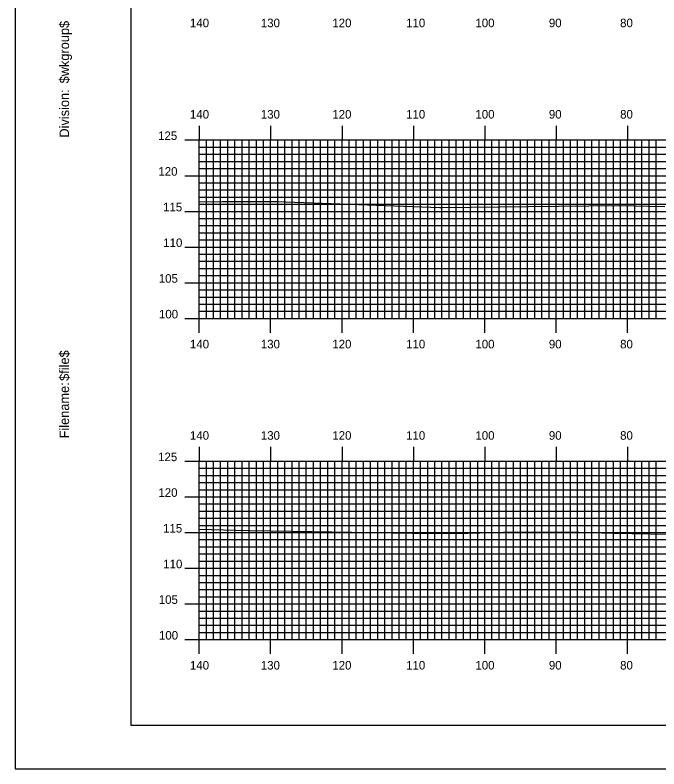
# Model space of a CAD drawing. Extents: x 1779893 to 1780236, y 442591 to 442811.
# Drawn here: x 1779892.6 to 1779982.7, y 442590.5 to 442696.2 of the extents above; entities that cross this region are included whole.
import ezdxf

# ---------------------------------------------------------------- set-up
doc = ezdxf.new("R2010")
doc.units = 0
for name, color, linetype in [('BORDER', 7, 'Continuous'), ('H_V ANNOTATION', 7, 'Continuous'), ('MAJOR', 7, 'Continuous'), ('MINOR', 7, 'Continuous'), ('PLOT BOUNDARY', 7, 'Continuous'), ('S_Roadway_Centerline', 7, 'Continuous')]:
    doc.layers.add(name, color=color, linetype=linetype)

msp = doc.modelspace()

# ---------------------------------------------------------------- linework, layer by layer
at = {"layer": 'BORDER'}
msp.add_lwpolyline([(1779908.76, 442596.67), (1780228.76, 442596.67), (1780228.76, 442806.67), (1779908.76, 442806.67)], close=True, dxfattribs=at)
at = {"layer": 'MAJOR'}
for p, q in [((1779918.36, 442680.67), (1779918.36, 442678.67)), ((1779928.36, 442680.67), (1779928.36, 442678.67)), ((1779938.36, 442680.67), (1779938.36, 442678.67)), ((1779948.36, 442680.67), (1779948.36, 442678.67)), ((1779958.36, 442680.67), (1779958.36, 442678.67)), ((1779968.36, 442680.67), (1779968.36, 442678.67)), ((1779978.36, 442680.67), (1779978.36, 442678.67)), ((1779916.35, 442678.67), (1779918.36, 442678.67)), ((1779918.36, 442678.67), (1780198.36, 442678.67)), ((1779918.36, 442653.67), (1779918.36, 442678.67)), ((1779918.36, 442653.67), (1779918.36, 442678.67)), ((1779918.36, 442678.67), (1780198.36, 442678.67)), ((1779928.36, 442653.67), (1779928.36, 442678.67)), ((1779938.36, 442653.67), (1779938.36, 442678.67)), ((1779948.36, 442653.67), (1779948.36, 442678.67)), ((1779958.36, 442653.67), (1779958.36, 442678.67)), ((1779968.36, 442653.67), (1779968.36, 442678.67)), ((1779978.36, 442653.67), (1779978.36, 442678.67)), ((1779916.35, 442673.67), (1779918.36, 442673.67)), ((1779918.36, 442673.67), (1780198.36, 442673.67)), ((1779916.35, 442668.67), (1779918.36, 442668.67)), ((1779918.36, 442668.67), (1780198.36, 442668.67)), ((1779916.35, 442663.67), (1779918.36, 442663.67)), ((1779918.36, 442663.67), (1780198.36, 442663.67)), ((1779916.35, 442658.67), (1779918.36, 442658.67)), ((1779918.36, 442658.67), (1780198.36, 442658.67)), ((1779916.35, 442653.67), (1779918.36, 442653.67)), ((1779918.36, 442653.67), (1780198.36, 442653.67)), ((1779918.36, 442653.67), (1780198.36, 442653.67)), ((1779918.36, 442651.66), (1779918.36, 442653.67)), ((1779928.36, 442651.66), (1779928.36, 442653.67)), ((1779938.36, 442651.66), (1779938.36, 442653.67)), ((1779948.36, 442651.66), (1779948.36, 442653.67)), ((1779958.36, 442651.66), (1779958.36, 442653.67)), ((1779968.36, 442651.66), (1779968.36, 442653.67)), ((1779978.36, 442651.66), (1779978.36, 442653.67)), ((1779918.36, 442635.67), (1779918.36, 442633.67)), ((1779928.36, 442635.67), (1779928.36, 442633.67)), ((1779938.36, 442635.67), (1779938.36, 442633.67)), ((1779948.36, 442635.67), (1779948.36, 442633.67)), ((1779958.36, 442635.67), (1779958.36, 442633.67)), ((1779968.36, 442635.67), (1779968.36, 442633.67)), ((1779978.36, 442635.67), (1779978.36, 442633.67)), ((1779916.35, 442633.67), (1779918.36, 442633.67)), ((1779918.36, 442633.67), (1780198.36, 442633.67)), ((1779918.36, 442608.67), (1779918.36, 442633.67)), ((1779918.36, 442608.67), (1779918.36, 442633.67)), ((1779918.36, 442633.67), (1780198.36, 442633.67)), ((1779928.36, 442608.67), (1779928.36, 442633.67)), ((1779938.36, 442608.67), (1779938.36, 442633.67)), ((1779948.36, 442608.67), (1779948.36, 442633.67)), ((1779958.36, 442608.67), (1779958.36, 442633.67)), ((1779968.36, 442608.67), (1779968.36, 442633.67)), ((1779978.36, 442608.67), (1779978.36, 442633.67)), ((1779916.35, 442628.67), (1779918.36, 442628.67)), ((1779918.36, 442628.67), (1780198.36, 442628.67)), ((1779916.35, 442623.67), (1779918.36, 442623.67)), ((1779918.36, 442623.67), (1780198.36, 442623.67)), ((1779916.35, 442618.67), (1779918.36, 442618.67)), ((1779918.36, 442618.67), (1780198.36, 442618.67)), ((1779916.35, 442613.67), (1779918.36, 442613.67)), ((1779918.36, 442613.67), (1780198.36, 442613.67)), ((1779916.35, 442608.67), (1779918.36, 442608.67)), ((1779918.36, 442608.67), (1780198.36, 442608.67)), ((1779918.36, 442608.67), (1780198.36, 442608.67)), ((1779918.36, 442606.66), (1779918.36, 442608.67)), ((1779928.36, 442606.66), (1779928.36, 442608.67)), ((1779938.36, 442606.66), (1779938.36, 442608.67)), ((1779948.36, 442606.66), (1779948.36, 442608.67)), ((1779958.36, 442606.66), (1779958.36, 442608.67)), ((1779968.36, 442606.66), (1779968.36, 442608.67)), ((1779978.36, 442606.66), (1779978.36, 442608.67))]:
    msp.add_line(p, q, dxfattribs=at)
at = {"layer": 'MINOR'}
for p, q in [((1779919.36, 442653.67), (1779919.36, 442678.67)), ((1779920.36, 442653.67), (1779920.36, 442678.67)), ((1779921.36, 442653.67), (1779921.36, 442678.67)), ((1779922.36, 442653.67), (1779922.36, 442678.67)), ((1779923.36, 442653.67), (1779923.36, 442678.67)), ((1779924.36, 442653.67), (1779924.36, 442678.67)), ((1779925.36, 442653.67), (1779925.36, 442678.67)), ((1779926.36, 442653.67), (1779926.36, 442678.67)), ((1779927.36, 442653.67), (1779927.36, 442678.67)), ((1779929.36, 442653.67), (1779929.36, 442678.67)), ((1779930.36, 442653.67), (1779930.36, 442678.67)), ((1779931.36, 442653.67), (1779931.36, 442678.67)), ((1779932.36, 442653.67), (1779932.36, 442678.67)), ((1779933.36, 442653.67), (1779933.36, 442678.67)), ((1779934.36, 442653.67), (1779934.36, 442678.67)), ((1779935.36, 442653.67), (1779935.36, 442678.67)), ((1779936.36, 442653.67), (1779936.36, 442678.67)), ((1779937.36, 442653.67), (1779937.36, 442678.67)), ((1779939.36, 442653.67), (1779939.36, 442678.67)), ((1779940.36, 442653.67), (1779940.36, 442678.67)), ((1779941.36, 442653.67), (1779941.36, 442678.67)), ((1779942.36, 442653.67), (1779942.36, 442678.67)), ((1779943.36, 442653.67), (1779943.36, 442678.67)), ((1779944.36, 442653.67), (1779944.36, 442678.67)), ((1779945.36, 442653.67), (1779945.36, 442678.67)), ((1779946.36, 442653.67), (1779946.36, 442678.67)), ((1779947.36, 442653.67), (1779947.36, 442678.67)), ((1779949.36, 442653.67), (1779949.36, 442678.67)), ((1779950.36, 442653.67), (1779950.36, 442678.67)), ((1779951.36, 442653.67), (1779951.36, 442678.67)), ((1779952.36, 442653.67), (1779952.36, 442678.67)), ((1779953.36, 442653.67), (1779953.36, 442678.67)), ((1779954.36, 442653.67), (1779954.36, 442678.67)), ((1779955.36, 442653.67), (1779955.36, 442678.67)), ((1779956.36, 442653.67), (1779956.36, 442678.67)), ((1779957.36, 442653.67), (1779957.36, 442678.67)), ((1779959.36, 442653.67), (1779959.36, 442678.67)), ((1779960.36, 442653.67), (1779960.36, 442678.67)), ((1779961.36, 442653.67), (1779961.36, 442678.67)), ((1779962.36, 442653.67), (1779962.36, 442678.67)), ((1779963.36, 442653.67), (1779963.36, 442678.67)), ((1779964.36, 442653.67), (1779964.36, 442678.67)), ((1779965.36, 442653.67), (1779965.36, 442678.67)), ((1779966.36, 442653.67), (1779966.36, 442678.67)), ((1779967.36, 442653.67), (1779967.36, 442678.67)), ((1779969.36, 442653.67), (1779969.36, 442678.67)), ((1779970.36, 442653.67), (1779970.36, 442678.67)), ((1779971.36, 442653.67), (1779971.36, 442678.67)), ((1779972.36, 442653.67), (1779972.36, 442678.67)), ((1779973.36, 442653.67), (1779973.36, 442678.67)), ((1779974.36, 442653.67), (1779974.36, 442678.67)), ((1779975.36, 442653.67), (1779975.36, 442678.67)), ((1779976.36, 442653.67), (1779976.36, 442678.67)), ((1779977.36, 442653.67), (1779977.36, 442678.67)), ((1779979.36, 442653.67), (1779979.36, 442678.67)), ((1779980.36, 442653.67), (1779980.36, 442678.67)), ((1779981.36, 442653.67), (1779981.36, 442678.67)), ((1779982.36, 442653.67), (1779982.36, 442678.67)), ((1779918.36, 442677.67), (1780198.36, 442677.67)), ((1779918.36, 442677.67), (1779920.36, 442677.67)), ((1779918.36, 442676.67), (1780198.36, 442676.67)), ((1779918.36, 442676.67), (1779920.36, 442676.67)), ((1779918.36, 442675.67), (1780198.36, 442675.67)), ((1779918.36, 442675.67), (1779920.36, 442675.67)), ((1779918.36, 442674.67), (1780198.36, 442674.67)), ((1779918.36, 442674.67), (1779920.36, 442674.67)), ((1779918.36, 442672.67), (1780198.36, 442672.67)), ((1779918.36, 442672.67), (1779920.36, 442672.67)), ((1779918.36, 442671.67), (1780198.36, 442671.67)), ((1779918.36, 442671.67), (1779920.36, 442671.67)), ((1779918.36, 442670.67), (1780198.36, 442670.67)), ((1779918.36, 442670.67), (1779920.36, 442670.67)), ((1779918.36, 442669.67), (1780198.36, 442669.67)), ((1779918.36, 442669.67), (1779920.36, 442669.67)), ((1779918.36, 442667.67), (1780198.36, 442667.67)), ((1779918.36, 442667.67), (1779920.36, 442667.67)), ((1779918.36, 442666.67), (1780198.36, 442666.67)), ((1779918.36, 442666.67), (1779920.36, 442666.67)), ((1779918.36, 442665.67), (1780198.36, 442665.67)), ((1779918.36, 442665.67), (1779920.36, 442665.67)), ((1779918.36, 442664.67), (1780198.36, 442664.67)), ((1779918.36, 442664.67), (1779920.36, 442664.67)), ((1779918.36, 442662.67), (1780198.36, 442662.67)), ((1779918.36, 442662.67), (1779920.36, 442662.67)), ((1779918.36, 442661.67), (1780198.36, 442661.67)), ((1779918.36, 442661.67), (1779920.36, 442661.67)), ((1779918.36, 442660.67), (1780198.36, 442660.67)), ((1779918.36, 442660.67), (1779920.36, 442660.67)), ((1779918.36, 442659.67), (1780198.36, 442659.67)), ((1779918.36, 442659.67), (1779920.36, 442659.67)), ((1779918.36, 442657.67), (1780198.36, 442657.67)), ((1779918.36, 442657.67), (1779920.36, 442657.67)), ((1779918.36, 442656.67), (1780198.36, 442656.67)), ((1779918.36, 442656.67), (1779920.36, 442656.67)), ((1779918.36, 442655.67), (1780198.36, 442655.67)), ((1779918.36, 442655.67), (1779920.36, 442655.67)), ((1779918.36, 442654.67), (1780198.36, 442654.67)), ((1779918.36, 442654.67), (1779920.36, 442654.67)), ((1779919.36, 442608.67), (1779919.36, 442633.67)), ((1779920.36, 442608.67), (1779920.36, 442633.67)), ((1779921.36, 442608.67), (1779921.36, 442633.67)), ((1779922.36, 442608.67), (1779922.36, 442633.67)), ((1779923.36, 442608.67), (1779923.36, 442633.67)), ((1779924.36, 442608.67), (1779924.36, 442633.67)), ((1779925.36, 442608.67), (1779925.36, 442633.67)), ((1779926.36, 442608.67), (1779926.36, 442633.67)), ((1779927.36, 442608.67), (1779927.36, 442633.67)), ((1779929.36, 442608.67), (1779929.36, 442633.67)), ((1779930.36, 442608.67), (1779930.36, 442633.67)), ((1779931.36, 442608.67), (1779931.36, 442633.67)), ((1779932.36, 442608.67), (1779932.36, 442633.67)), ((1779933.36, 442608.67), (1779933.36, 442633.67)), ((1779934.36, 442608.67), (1779934.36, 442633.67)), ((1779935.36, 442608.67), (1779935.36, 442633.67)), ((1779936.36, 442608.67), (1779936.36, 442633.67)), ((1779937.36, 442608.67), (1779937.36, 442633.67)), ((1779939.36, 442608.67), (1779939.36, 442633.67)), ((1779940.36, 442608.67), (1779940.36, 442633.67)), ((1779941.36, 442608.67), (1779941.36, 442633.67)), ((1779942.36, 442608.67), (1779942.36, 442633.67)), ((1779943.36, 442608.67), (1779943.36, 442633.67)), ((1779944.36, 442608.67), (1779944.36, 442633.67)), ((1779945.36, 442608.67), (1779945.36, 442633.67)), ((1779946.36, 442608.67), (1779946.36, 442633.67)), ((1779947.36, 442608.67), (1779947.36, 442633.67)), ((1779949.36, 442608.67), (1779949.36, 442633.67)), ((1779950.36, 442608.67), (1779950.36, 442633.67)), ((1779951.36, 442608.67), (1779951.36, 442633.67)), ((1779952.36, 442608.67), (1779952.36, 442633.67)), ((1779953.36, 442608.67), (1779953.36, 442633.67)), ((1779954.36, 442608.67), (1779954.36, 442633.67)), ((1779955.36, 442608.67), (1779955.36, 442633.67)), ((1779956.36, 442608.67), (1779956.36, 442633.67)), ((1779957.36, 442608.67), (1779957.36, 442633.67)), ((1779959.36, 442608.67), (1779959.36, 442633.67)), ((1779960.36, 442608.67), (1779960.36, 442633.67)), ((1779961.36, 442608.67), (1779961.36, 442633.67)), ((1779962.36, 442608.67), (1779962.36, 442633.67)), ((1779963.36, 442608.67), (1779963.36, 442633.67)), ((1779964.36, 442608.67), (1779964.36, 442633.67)), ((1779965.36, 442608.67), (1779965.36, 442633.67)), ((1779966.36, 442608.67), (1779966.36, 442633.67)), ((1779967.36, 442608.67), (1779967.36, 442633.67)), ((1779969.36, 442608.67), (1779969.36, 442633.67)), ((1779970.36, 442608.67), (1779970.36, 442633.67)), ((1779971.36, 442608.67), (1779971.36, 442633.67)), ((1779972.36, 442608.67), (1779972.36, 442633.67)), ((1779973.36, 442608.67), (1779973.36, 442633.67)), ((1779974.36, 442608.67), (1779974.36, 442633.67)), ((1779975.36, 442608.67), (1779975.36, 442633.67)), ((1779976.36, 442608.67), (1779976.36, 442633.67)), ((1779977.36, 442608.67), (1779977.36, 442633.67)), ((1779979.36, 442608.67), (1779979.36, 442633.67)), ((1779980.36, 442608.67), (1779980.36, 442633.67)), ((1779981.36, 442608.67), (1779981.36, 442633.67)), ((1779982.36, 442608.67), (1779982.36, 442633.67)), ((1779918.36, 442632.67), (1780198.36, 442632.67)), ((1779918.36, 442632.67), (1779920.36, 442632.67)), ((1779918.36, 442631.67), (1780198.36, 442631.67)), ((1779918.36, 442631.67), (1779920.36, 442631.67)), ((1779918.36, 442630.67), (1780198.36, 442630.67)), ((1779918.36, 442630.67), (1779920.36, 442630.67)), ((1779918.36, 442629.67), (1780198.36, 442629.67)), ((1779918.36, 442629.67), (1779920.36, 442629.67)), ((1779918.36, 442627.67), (1780198.36, 442627.67)), ((1779918.36, 442627.67), (1779920.36, 442627.67)), ((1779918.36, 442626.67), (1780198.36, 442626.67)), ((1779918.36, 442626.67), (1779920.36, 442626.67)), ((1779918.36, 442625.67), (1780198.36, 442625.67)), ((1779918.36, 442625.67), (1779920.36, 442625.67)), ((1779918.36, 442624.67), (1780198.36, 442624.67)), ((1779918.36, 442624.67), (1779920.36, 442624.67)), ((1779918.36, 442622.67), (1780198.36, 442622.67)), ((1779918.36, 442622.67), (1779920.36, 442622.67)), ((1779918.36, 442621.67), (1780198.36, 442621.67)), ((1779918.36, 442621.67), (1779920.36, 442621.67)), ((1779918.36, 442620.67), (1780198.36, 442620.67)), ((1779918.36, 442620.67), (1779920.36, 442620.67)), ((1779918.36, 442619.67), (1780198.36, 442619.67)), ((1779918.36, 442619.67), (1779920.36, 442619.67)), ((1779918.36, 442617.67), (1780198.36, 442617.67)), ((1779918.36, 442617.67), (1779920.36, 442617.67)), ((1779918.36, 442616.67), (1780198.36, 442616.67)), ((1779918.36, 442616.67), (1779920.36, 442616.67)), ((1779918.36, 442615.67), (1780198.36, 442615.67)), ((1779918.36, 442615.67), (1779920.36, 442615.67)), ((1779918.36, 442614.67), (1780198.36, 442614.67)), ((1779918.36, 442614.67), (1779920.36, 442614.67)), ((1779918.36, 442612.67), (1780198.36, 442612.67)), ((1779918.36, 442612.67), (1779920.36, 442612.67)), ((1779918.36, 442611.67), (1780198.36, 442611.67)), ((1779918.36, 442611.67), (1779920.36, 442611.67)), ((1779918.36, 442610.67), (1780198.36, 442610.67)), ((1779918.36, 442610.67), (1779920.36, 442610.67)), ((1779918.36, 442609.67), (1780198.36, 442609.67)), ((1779918.36, 442609.67), (1779920.36, 442609.67))]:
    msp.add_line(p, q, dxfattribs=at)
at = {"layer": 'PLOT BOUNDARY'}
msp.add_lwpolyline([(1779892.57, 442590.55), (1780232.57, 442590.55), (1780232.57, 442810.55), (1779892.57, 442810.55)], close=True, dxfattribs=at)
at = {"layer": 'S_Roadway_Centerline'}
for points in [[(1779918.36, 442670.02), (1779921.58, 442670.03), (1779929.05, 442670.03), (1779929.25, 442670.03), (1779952.07, 442669.22), (1779952.25, 442669.22), (1779952.41, 442669.23), (1779964.49, 442669.37), (1779977.17, 442669.48), (1779983.58, 442669.33)], [(1779918.36, 442624.13), (1779925.22, 442623.97), (1779931.35, 442623.86), (1779948.17, 442623.57), (1779954.34, 442623.55), (1779962.59, 442623.75), (1779971.54, 442623.7), (1779976.32, 442623.59), (1779986.82, 442623.38)]]:
    msp.add_lwpolyline(points, dxfattribs=at)

# ---------------------------------------------------------------- texts
at = {"layer": 'BORDER'}
for s, p in [('$wkgroup$', (1779900.13, 442686.6)), ('Division:', (1779900.13, 442679)), ('$file$', (1779900.13, 442644.92)), ('Filename:', (1779900.13, 442636.86))]:
    msp.add_text(s, height=1.339, rotation=90, dxfattribs=at).set_placement(p)
at = {"layer": 'H_V ANNOTATION'}
for s, p in [('140', (1779917.06, 442694.47)), ('130', (1779926.99, 442694.47)), ('120', (1779937, 442694.47)), ('110', (1779947.34, 442694.47)), ('100', (1779957.04, 442694.47)), ('90', (1779967.33, 442694.47)), ('80', (1779977.31, 442694.47)), ('140', (1779917.06, 442681.67)), ('130', (1779926.99, 442681.67)), ('120', (1779937, 442681.67)), ('110', (1779947.34, 442681.67)), ('100', (1779957.04, 442681.67)), ('90', (1779967.33, 442681.67)), ('80', (1779977.31, 442681.67)), ('125', (1779912.6, 442678.67)), ('120', (1779912.64, 442673.67)), ('115', (1779913.29, 442668.67)), ('110', (1779913.32, 442663.67)), ('105', (1779912.69, 442658.67)), ('100', (1779912.72, 442653.67)), ('140', (1779917.06, 442649.47)), ('130', (1779926.99, 442649.47)), ('120', (1779937, 442649.47)), ('110', (1779947.34, 442649.47)), ('100', (1779957.04, 442649.47)), ('90', (1779967.33, 442649.47)), ('80', (1779977.31, 442649.47)), ('140', (1779917.06, 442636.67)), ('130', (1779926.99, 442636.67)), ('120', (1779937, 442636.67)), ('110', (1779947.34, 442636.67)), ('100', (1779957.04, 442636.67)), ('90', (1779967.33, 442636.67)), ('80', (1779977.31, 442636.67)), ('125', (1779912.6, 442633.67)), ('120', (1779912.64, 442628.67)), ('115', (1779913.29, 442623.67)), ('110', (1779913.32, 442618.67)), ('105', (1779912.69, 442613.67)), ('100', (1779912.72, 442608.67)), ('140', (1779917.06, 442604.47)), ('130', (1779926.99, 442604.47)), ('120', (1779937, 442604.47)), ('110', (1779947.34, 442604.47)), ('100', (1779957.04, 442604.47)), ('90', (1779967.33, 442604.47)), ('80', (1779977.31, 442604.47))]:
    msp.add_text(s, height=1.2, dxfattribs=at).set_placement(p)
at = {"layer": 'MAJOR'}
for p in [(1779918.35, 442653.67), (1779918.35, 442608.67)]:
    msp.add_text('-', height=0.012, dxfattribs=at).set_placement(p)

doc.saveas('drawing.dxf')
